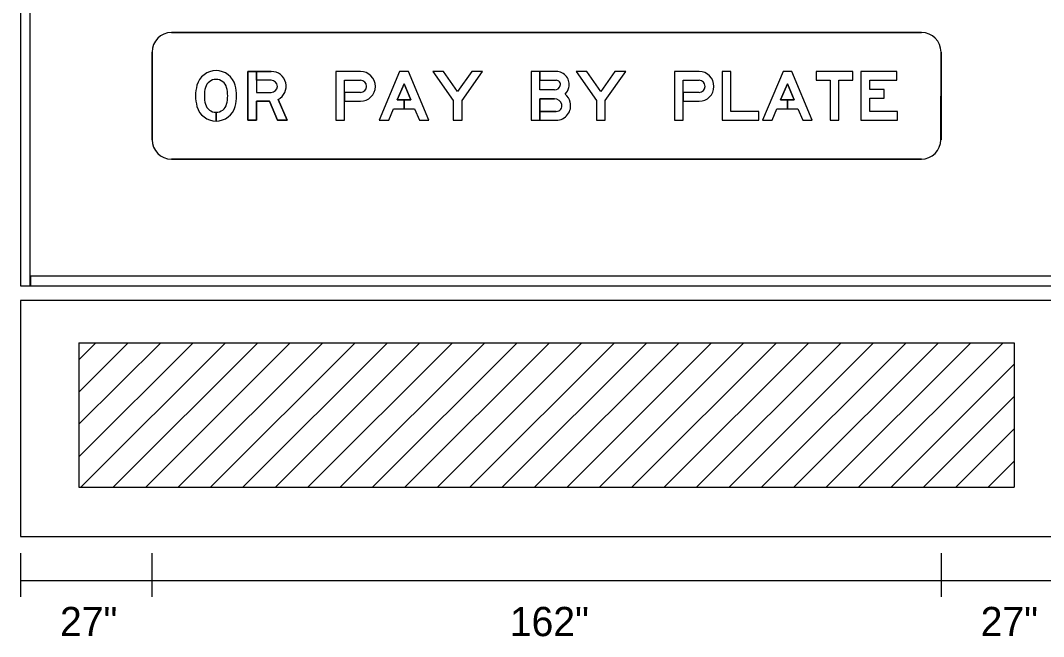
# Model space of a CAD drawing. Extents: x 10268312 to 10268472, y 2142583 to 2142688.
# Drawn here: x 10268433.44 to 10268458.14, y 2142658.39 to 2142673.26 of the extents above; entities that cross this region are included whole.
import ezdxf

# ---------------------------------------------------------------- set-up
doc = ezdxf.new("R2010")
doc.units = 0
for name, color, linetype in [('GSBWFill', 7, 'Continuous'), ('GSDims', 7, 'Continuous'), ('SignPanel', 7, 'Continuous'), ('TextMisc', 7, 'Continuous')]:
    doc.layers.add(name, color=color, linetype=linetype)

msp = doc.modelspace()

# ---------------------------------------------------------------- linework, layer by layer
at = {"layer": 'GSBWFill'}
for p, q in [((10268437.092, 2142672.972), (10268455.198, 2142672.972)), ((10268437.092, 2142672.972), (10268455.198, 2142672.972)), ((10268436.622, 2142670.384), (10268436.622, 2142672.501)), ((10268436.622, 2142670.384), (10268436.622, 2142672.501)), ((10268455.668, 2142672.501), (10268455.668, 2142670.384)), ((10268455.668, 2142672.501), (10268455.668, 2142670.384)), ((10268455.198, 2142669.914), (10268437.092, 2142669.914)), ((10268455.198, 2142669.914), (10268437.092, 2142669.914))]:
    msp.add_line(p, q, dxfattribs=at)
for points in [[(10268433.445, 2142682.673), (10268433.445, 2142666.857), (10268433.68, 2142666.857), (10268433.68, 2142682.673)], [(10268458.61, 2142667.092), (10268433.687, 2142667.092), (10268433.687, 2142666.857), (10268458.845, 2142666.857), (10268458.845, 2142666.857), (10268458.845, 2142682.673)]]:
    msp.add_lwpolyline(points, dxfattribs=at)
for centre, start, end in [((10268437.092, 2142672.501), 90, 180), ((10268437.092, 2142672.501), 90, 180), ((10268455.198, 2142672.501), 0, 90), ((10268455.198, 2142672.501), 0, 90), ((10268437.092, 2142670.384), 180, 270), ((10268437.092, 2142670.384), 180, 270), ((10268455.193, 2142670.384), 270, 0), ((10268455.193, 2142670.384), 270, 0)]:
    msp.add_arc(centre, 0.47, start, end, dxfattribs=at)
at = {"layer": 'GSDims'}
for p, q in [((10268433.445, 2142660.403), (10268433.445, 2142659.345)), ((10268436.62, 2142660.403), (10268436.62, 2142659.345)), ((10268455.67, 2142660.403), (10268455.67, 2142659.345)), ((10268433.445, 2142659.742), (10268436.62, 2142659.742)), ((10268436.62, 2142659.742), (10268455.67, 2142659.742)), ((10268455.67, 2142659.742), (10268458.845, 2142659.742))]:
    msp.add_line(p, q, dxfattribs=at)
at = {"layer": 'SignPanel'}
for p, q in [((10268455.198, 2142672.972), (10268437.092, 2142672.972)), ((10268436.622, 2142672.501), (10268436.622, 2142670.384)), ((10268455.664, 2142670.384), (10268455.668, 2142672.501)), ((10268441.271, 2142671.819), (10268441.653, 2142671.819)), ((10268441.271, 2142671.819), (10268441.653, 2142671.819)), ((10268441.271, 2142671.819), (10268441.653, 2142671.819)), ((10268449.444, 2142671.819), (10268449.826, 2142671.819)), ((10268449.444, 2142671.819), (10268449.826, 2142671.819)), ((10268449.444, 2142671.819), (10268449.826, 2142671.819)), ((10268441.271, 2142671.313), (10268441.653, 2142671.313)), ((10268449.444, 2142671.313), (10268449.826, 2142671.313)), ((10268438.166, 2142670.834), (10268438.166, 2142671.046)), ((10268438.166, 2142671.046), (10268438.166, 2142670.834)), ((10268438.166, 2142670.834), (10268438.166, 2142671.046)), ((10268438.166, 2142671.046), (10268438.166, 2142670.834)), ((10268445.775, 2142670.855), (10268446.38, 2142670.855)), ((10268437.092, 2142669.914), (10268455.193, 2142669.914)), ((10268458.845, 2142666.504), (10268433.445, 2142666.504)), ((10268433.445, 2142666.504), (10268433.445, 2142660.8)), ((10268433.445, 2142660.8), (10268458.845, 2142660.8))]:
    msp.add_line(p, q, dxfattribs=at)
for points in [[(10268439.499, 2142672.031), (10268438.93, 2142672.031), (10268438.93, 2142670.855), (10268439.142, 2142670.855), (10268439.142, 2142671.313), (10268439.454, 2142671.313), (10268439.652, 2142670.855), (10268439.883, 2142670.855), (10268439.666, 2142671.355)], [(10268439.666, 2142671.355), (10268439.883, 2142670.855), (10268439.652, 2142670.855), (10268439.454, 2142671.313), (10268439.142, 2142671.313), (10268439.142, 2142670.855), (10268438.93, 2142670.855), (10268438.93, 2142672.031), (10268439.142, 2142672.031), (10268439.142, 2142671.525), (10268439.499, 2142671.525)], [(10268439.666, 2142671.355), (10268439.883, 2142670.855), (10268439.652, 2142670.855), (10268439.454, 2142671.313), (10268439.142, 2142671.313), (10268439.142, 2142670.855), (10268438.93, 2142670.855), (10268438.93, 2142672.031), (10268439.142, 2142672.031), (10268439.142, 2142671.525), (10268439.499, 2142671.525)], [(10268439.142, 2142671.819), (10268439.142, 2142672.031), (10268439.499, 2142672.031)], [(10268439.142, 2142671.819), (10268439.142, 2142672.031), (10268439.499, 2142672.031)], [(10268441.653, 2142672.031), (10268441.059, 2142672.031), (10268441.059, 2142670.855), (10268441.271, 2142670.855), (10268441.271, 2142671.313)], [(10268441.653, 2142672.031), (10268441.059, 2142672.031), (10268441.059, 2142670.855), (10268441.271, 2142670.855), (10268441.271, 2142671.819)], [(10268441.653, 2142672.031), (10268441.059, 2142672.031), (10268441.059, 2142670.855), (10268441.271, 2142670.855), (10268441.271, 2142671.819)], [(10268446.38, 2142672.031), (10268445.775, 2142672.031), (10268445.775, 2142670.855)], [(10268446.335, 2142671.584), (10268445.986, 2142671.584), (10268445.986, 2142672.031), (10268445.775, 2142672.031), (10268445.775, 2142670.855), (10268445.986, 2142670.855)], [(10268446.335, 2142671.584), (10268445.986, 2142671.584), (10268445.986, 2142672.031), (10268445.775, 2142672.031), (10268445.775, 2142670.855), (10268445.986, 2142670.855)], [(10268446.38, 2142672.031), (10268445.986, 2142672.031), (10268445.986, 2142671.819), (10268446.38, 2142671.819)], [(10268446.38, 2142672.031), (10268445.986, 2142672.031), (10268445.986, 2142671.819), (10268446.38, 2142671.819)], [(10268449.826, 2142672.031), (10268449.232, 2142672.031), (10268449.232, 2142670.855), (10268449.444, 2142670.855), (10268449.444, 2142671.313)], [(10268449.826, 2142672.031), (10268449.232, 2142672.031), (10268449.232, 2142670.855), (10268449.444, 2142670.855), (10268449.444, 2142671.819)], [(10268449.826, 2142672.031), (10268449.232, 2142672.031), (10268449.232, 2142670.855), (10268449.444, 2142670.855), (10268449.444, 2142671.819)], [(10268439.499, 2142671.819), (10268439.142, 2142671.819), (10268439.142, 2142671.525), (10268439.499, 2142671.525)], [(10268439.499, 2142671.819), (10268439.142, 2142671.819)], [(10268439.499, 2142671.819), (10268439.142, 2142671.819)], [(10268441.653, 2142671.525), (10268441.271, 2142671.525), (10268441.271, 2142671.819)], [(10268446.335, 2142671.584), (10268445.986, 2142671.584), (10268445.986, 2142671.819), (10268446.38, 2142671.819)], [(10268449.826, 2142671.525), (10268449.444, 2142671.525), (10268449.444, 2142671.819)], [(10268441.653, 2142671.525), (10268441.271, 2142671.525), (10268441.271, 2142671.313), (10268441.653, 2142671.313)], [(10268441.653, 2142671.525), (10268441.271, 2142671.525), (10268441.271, 2142671.313), (10268441.653, 2142671.313)], [(10268449.826, 2142671.525), (10268449.444, 2142671.525), (10268449.444, 2142671.313), (10268449.826, 2142671.313)], [(10268449.826, 2142671.525), (10268449.444, 2142671.525), (10268449.444, 2142671.313), (10268449.826, 2142671.313)], [(10268446.335, 2142671.372), (10268445.986, 2142671.372), (10268445.986, 2142671.066), (10268446.38, 2142671.066)], [(10268445.986, 2142670.855), (10268445.986, 2142671.372), (10268446.335, 2142671.372)], [(10268445.986, 2142670.855), (10268445.986, 2142671.372), (10268446.335, 2142671.372)], [(10268446.38, 2142671.066), (10268445.986, 2142671.066), (10268445.986, 2142670.855), (10268446.38, 2142670.855)], [(10268446.38, 2142671.066), (10268445.986, 2142671.066), (10268445.986, 2142670.855), (10268446.38, 2142670.855)]]:
    msp.add_lwpolyline(points, dxfattribs=at)
for points in [[(10268442.451, 2142671.131), (10268442.959, 2142671.131), (10268443.075, 2142670.855), (10268443.305, 2142670.855), (10268442.811, 2142672.031), (10268442.599, 2142672.031), (10268442.106, 2142670.855), (10268442.335, 2142670.855)], [(10268442.871, 2142671.343), (10268442.705, 2142671.343), (10268442.705, 2142671.131), (10268442.959, 2142671.131), (10268443.075, 2142670.855), (10268443.305, 2142670.855), (10268442.811, 2142672.031), (10268442.599, 2142672.031), (10268442.106, 2142670.855), (10268442.335, 2142670.855), (10268442.451, 2142671.131), (10268442.705, 2142671.131), (10268442.705, 2142671.343), (10268442.54, 2142671.343), (10268442.705, 2142671.736)], [(10268442.871, 2142671.343), (10268442.705, 2142671.343), (10268442.705, 2142671.131), (10268442.959, 2142671.131), (10268443.075, 2142670.855), (10268443.305, 2142670.855), (10268442.811, 2142672.031), (10268442.599, 2142672.031), (10268442.106, 2142670.855), (10268442.335, 2142670.855), (10268442.451, 2142671.131), (10268442.705, 2142671.131), (10268442.705, 2142671.343), (10268442.54, 2142671.343), (10268442.705, 2142671.736)], [(10268444.105, 2142671.331), (10268444.599, 2142672.031), (10268444.34, 2142672.031), (10268443.999, 2142671.548), (10268443.658, 2142672.031), (10268443.399, 2142672.031), (10268443.893, 2142671.331), (10268443.893, 2142670.855), (10268444.105, 2142670.855)], [(10268444.105, 2142671.331), (10268444.599, 2142672.031), (10268444.34, 2142672.031), (10268443.999, 2142671.548), (10268443.658, 2142672.031), (10268443.399, 2142672.031), (10268443.893, 2142671.331), (10268443.893, 2142670.855), (10268444.105, 2142670.855)], [(10268444.105, 2142671.331), (10268444.599, 2142672.031), (10268444.34, 2142672.031), (10268443.999, 2142671.548), (10268443.658, 2142672.031), (10268443.399, 2142672.031), (10268443.893, 2142671.331), (10268443.893, 2142670.855), (10268444.105, 2142670.855)], [(10268447.562, 2142671.331), (10268448.056, 2142672.031), (10268447.797, 2142672.031), (10268447.456, 2142671.548), (10268447.116, 2142672.031), (10268446.856, 2142672.031), (10268447.35, 2142671.331), (10268447.35, 2142670.855), (10268447.562, 2142670.855)], [(10268447.562, 2142671.331), (10268448.056, 2142672.031), (10268447.797, 2142672.031), (10268447.456, 2142671.548), (10268447.116, 2142672.031), (10268446.856, 2142672.031), (10268447.35, 2142671.331), (10268447.35, 2142670.855), (10268447.562, 2142670.855)], [(10268447.562, 2142671.331), (10268448.056, 2142672.031), (10268447.797, 2142672.031), (10268447.456, 2142671.548), (10268447.116, 2142672.031), (10268446.856, 2142672.031), (10268447.35, 2142671.331), (10268447.35, 2142670.855), (10268447.562, 2142670.855)], [(10268451.266, 2142670.855), (10268451.266, 2142671.061), (10268450.596, 2142671.061), (10268450.596, 2142672.031), (10268450.384, 2142672.031), (10268450.384, 2142670.855)], [(10268451.266, 2142670.855), (10268451.266, 2142671.061), (10268450.596, 2142671.061), (10268450.596, 2142672.031), (10268450.384, 2142672.031), (10268450.384, 2142670.855)], [(10268451.266, 2142670.855), (10268451.266, 2142671.061), (10268450.596, 2142671.061), (10268450.596, 2142672.031), (10268450.384, 2142672.031), (10268450.384, 2142670.855)], [(10268451.706, 2142671.131), (10268452.214, 2142671.131), (10268452.33, 2142670.855), (10268452.56, 2142670.855), (10268452.066, 2142672.031), (10268451.854, 2142672.031), (10268451.36, 2142670.855), (10268451.59, 2142670.855)], [(10268452.125, 2142671.343), (10268451.96, 2142671.343), (10268451.96, 2142671.131), (10268452.214, 2142671.131), (10268452.33, 2142670.855), (10268452.56, 2142670.855), (10268452.066, 2142672.031), (10268451.854, 2142672.031), (10268451.36, 2142670.855), (10268451.59, 2142670.855), (10268451.706, 2142671.131), (10268451.96, 2142671.131), (10268451.96, 2142671.343), (10268451.795, 2142671.343), (10268451.96, 2142671.736)], [(10268452.125, 2142671.343), (10268451.96, 2142671.343), (10268451.96, 2142671.131), (10268452.214, 2142671.131), (10268452.33, 2142670.855), (10268452.56, 2142670.855), (10268452.066, 2142672.031), (10268451.854, 2142672.031), (10268451.36, 2142670.855), (10268451.59, 2142670.855), (10268451.706, 2142671.131), (10268451.96, 2142671.131), (10268451.96, 2142671.343), (10268451.795, 2142671.343), (10268451.96, 2142671.736)], [(10268452.654, 2142671.819), (10268452.989, 2142671.819), (10268452.989, 2142670.855), (10268453.201, 2142670.855), (10268453.201, 2142671.819), (10268453.536, 2142671.819), (10268453.536, 2142672.031), (10268452.654, 2142672.031)], [(10268452.654, 2142671.819), (10268452.989, 2142671.819), (10268452.989, 2142670.855), (10268453.201, 2142670.855), (10268453.201, 2142671.819), (10268453.536, 2142671.819), (10268453.536, 2142672.031), (10268452.654, 2142672.031)], [(10268452.654, 2142671.819), (10268452.989, 2142671.819), (10268452.989, 2142670.855), (10268453.201, 2142670.855), (10268453.201, 2142671.819), (10268453.536, 2142671.819), (10268453.536, 2142672.031), (10268452.654, 2142672.031)], [(10268454.618, 2142671.066), (10268453.948, 2142671.066), (10268453.948, 2142671.383), (10268454.294, 2142671.383), (10268454.294, 2142671.594), (10268453.948, 2142671.594), (10268453.948, 2142671.819), (10268454.6, 2142671.819), (10268454.6, 2142672.031), (10268453.736, 2142672.031), (10268453.736, 2142670.855), (10268454.618, 2142670.855)], [(10268454.618, 2142671.066), (10268453.948, 2142671.066), (10268453.948, 2142671.383), (10268454.294, 2142671.383), (10268454.294, 2142671.594), (10268453.948, 2142671.594), (10268453.948, 2142671.819), (10268454.6, 2142671.819), (10268454.6, 2142672.031), (10268453.736, 2142672.031), (10268453.736, 2142670.855), (10268454.618, 2142670.855)], [(10268454.618, 2142671.066), (10268453.948, 2142671.066), (10268453.948, 2142671.383), (10268454.294, 2142671.383), (10268454.294, 2142671.594), (10268453.948, 2142671.594), (10268453.948, 2142671.819), (10268454.6, 2142671.819), (10268454.6, 2142672.031), (10268453.736, 2142672.031), (10268453.736, 2142670.855), (10268454.618, 2142670.855)], [(10268442.871, 2142671.343), (10268442.705, 2142671.736), (10268442.54, 2142671.343)], [(10268452.125, 2142671.343), (10268451.96, 2142671.736), (10268451.795, 2142671.343)]]:
    msp.add_lwpolyline(points, close=True, dxfattribs=at)
for centre, radius, start, end in [((10268437.092, 2142672.501), 0.47, 90, 180), ((10268455.198, 2142672.501), 0.47, 0, 90), ((10268438.166, 2142671.575), 0.477, 14.9618, 165.0382), ((10268438.166, 2142671.575), 0.477, 14.9618, 165.0382), ((10268438.166, 2142671.575), 0.477, 14.9618, 165.0382), ((10268439.499, 2142671.672), 0.359, 297.837, 90), ((10268439.499, 2142671.672), 0.359, 297.837, 90), ((10268439.499, 2142671.672), 0.359, 297.837, 90), ((10268441.653, 2142671.672), 0.359, 270, 90), ((10268441.653, 2142671.672), 0.359, 270, 90), ((10268441.653, 2142671.672), 0.359, 270, 90), ((10268446.38, 2142671.719), 0.312, 345.5225, 90), ((10268446.38, 2142671.719), 0.312, 345.5225, 90), ((10268446.38, 2142671.719), 0.312, 345.5225, 90), ((10268449.826, 2142671.672), 0.359, 270, 90), ((10268449.826, 2142671.672), 0.359, 270, 90), ((10268449.826, 2142671.672), 0.359, 270, 90), ((10268438.166, 2142671.575), 0.265, 14.9618, 165.0382), ((10268438.166, 2142671.575), 0.265, 14.9618, 165.0382), ((10268438.166, 2142671.575), 0.265, 14.9618, 165.0382), ((10268439.499, 2142671.672), 0.147, 270, 90), ((10268439.499, 2142671.672), 0.147, 270, 90), ((10268439.499, 2142671.672), 0.147, 270, 90), ((10268441.653, 2142671.672), 0.147, 270, 90), ((10268441.653, 2142671.672), 0.147, 270, 90), ((10268441.653, 2142671.672), 0.147, 270, 90), ((10268446.38, 2142671.719), 0.1, 345.5225, 90), ((10268446.38, 2142671.719), 0.1, 345.5225, 90), ((10268446.38, 2142671.719), 0.1, 345.5225, 90), ((10268449.826, 2142671.672), 0.147, 270, 90), ((10268449.826, 2142671.672), 0.147, 270, 90), ((10268449.826, 2142671.672), 0.147, 270, 90), ((10268438.66, 2142671.443), 0.988, 165.0382, 194.9618), ((10268438.66, 2142671.443), 0.988, 165.0382, 194.9618), ((10268438.66, 2142671.443), 0.988, 165.0382, 194.9618), ((10268438.66, 2142671.443), 0.776, 165.0382, 194.9618), ((10268438.66, 2142671.443), 0.776, 165.0382, 194.9618), ((10268438.66, 2142671.443), 0.776, 165.0382, 194.9618), ((10268437.672, 2142671.443), 0.776, 345.0382, 14.9618), ((10268437.672, 2142671.443), 0.776, 345.0382, 14.9618), ((10268437.672, 2142671.443), 0.776, 345.0382, 14.9618), ((10268437.672, 2142671.443), 0.988, 345.0382, 14.9618), ((10268437.672, 2142671.443), 0.988, 345.0382, 14.9618), ((10268437.672, 2142671.443), 0.988, 345.0382, 14.9618), ((10268446.335, 2142671.731), 0.147, 270, 345.5225), ((10268446.335, 2142671.731), 0.147, 270, 345.5225), ((10268446.335, 2142671.731), 0.147, 270, 345.5225), ((10268446.335, 2142671.731), 0.359, 316.7114, 345.5225), ((10268446.335, 2142671.731), 0.359, 316.7114, 345.5225), ((10268446.335, 2142671.731), 0.359, 316.7114, 345.5225), ((10268446.335, 2142671.19), 0.394, 14.4775, 48.4921), ((10268446.335, 2142671.19), 0.394, 14.4775, 48.4921), ((10268446.335, 2142671.19), 0.394, 14.4775, 48.4921), ((10268438.166, 2142671.311), 0.265, 194.9618, 345.0382), ((10268438.166, 2142671.311), 0.265, 194.9618, 270), ((10268438.166, 2142671.311), 0.265, 194.9618, 270), ((10268438.166, 2142671.311), 0.265, 270.0127, 345.0382), ((10268438.166, 2142671.311), 0.265, 270.0127, 345.0382), ((10268446.335, 2142671.19), 0.182, 14.4775, 90), ((10268446.335, 2142671.19), 0.182, 14.4775, 90), ((10268446.335, 2142671.19), 0.182, 14.4775, 90), ((10268446.38, 2142671.202), 0.347, 270, 14.4775), ((10268446.38, 2142671.202), 0.347, 270, 14.4775), ((10268446.38, 2142671.202), 0.347, 270, 14.4775), ((10268446.38, 2142671.202), 0.135, 270, 14.4775), ((10268446.38, 2142671.202), 0.135, 270, 14.4775), ((10268446.38, 2142671.202), 0.135, 270, 14.4775), ((10268438.166, 2142671.311), 0.477, 194.9618, 345.0382), ((10268438.166, 2142671.311), 0.477, 194.9618, 270), ((10268438.166, 2142671.311), 0.477, 194.9618, 270), ((10268438.166, 2142671.311), 0.477, 270.0071, 345.0382), ((10268438.166, 2142671.311), 0.477, 270.0071, 345.0382), ((10268437.092, 2142670.384), 0.47, 180, 270), ((10268455.193, 2142670.384), 0.47, 270, 0)]:
    msp.add_arc(centre, radius, start, end, dxfattribs=at)
at = {"layer": 'TextMisc'}
for p, q in [((10268434.856, 2142665.073), (10268435.265, 2142665.482)), ((10268434.856, 2142664.292), (10268436.048, 2142665.482)), ((10268434.856, 2142663.512), (10268436.83, 2142665.482)), ((10268434.856, 2142662.731), (10268437.612, 2142665.482)), ((10268434.856, 2142665.482), (10268457.434, 2142665.482)), ((10268434.856, 2142665.482), (10268434.856, 2142661.998)), ((10268434.904, 2142661.998), (10268438.395, 2142665.482)), ((10268435.686, 2142661.998), (10268439.177, 2142665.482)), ((10268436.469, 2142661.998), (10268439.959, 2142665.482)), ((10268437.251, 2142661.998), (10268440.741, 2142665.482)), ((10268438.033, 2142661.998), (10268441.524, 2142665.482)), ((10268438.816, 2142661.998), (10268442.306, 2142665.482)), ((10268439.598, 2142661.998), (10268443.088, 2142665.482)), ((10268440.38, 2142661.998), (10268443.871, 2142665.482)), ((10268441.162, 2142661.998), (10268444.653, 2142665.482)), ((10268441.945, 2142661.998), (10268445.435, 2142665.482)), ((10268442.727, 2142661.998), (10268446.218, 2142665.482)), ((10268443.509, 2142661.998), (10268447, 2142665.482)), ((10268444.292, 2142661.998), (10268447.782, 2142665.482)), ((10268445.074, 2142661.998), (10268448.565, 2142665.482)), ((10268445.856, 2142661.998), (10268449.347, 2142665.482)), ((10268446.639, 2142661.998), (10268450.129, 2142665.482)), ((10268447.421, 2142661.998), (10268450.911, 2142665.482)), ((10268448.203, 2142661.998), (10268451.694, 2142665.482)), ((10268448.985, 2142661.998), (10268452.476, 2142665.482)), ((10268449.768, 2142661.998), (10268453.258, 2142665.482)), ((10268450.55, 2142661.998), (10268454.041, 2142665.482)), ((10268451.332, 2142661.998), (10268454.823, 2142665.482)), ((10268452.115, 2142661.998), (10268455.605, 2142665.482)), ((10268452.897, 2142661.998), (10268456.388, 2142665.482)), ((10268453.679, 2142661.998), (10268457.17, 2142665.482)), ((10268457.434, 2142665.482), (10268457.434, 2142661.998)), ((10268454.462, 2142661.998), (10268457.434, 2142664.965)), ((10268455.244, 2142661.998), (10268457.434, 2142664.184)), ((10268456.026, 2142661.998), (10268457.434, 2142663.403)), ((10268456.809, 2142661.998), (10268457.434, 2142662.623)), ((10268434.856, 2142661.998), (10268457.434, 2142661.998))]:
    msp.add_line(p, q, dxfattribs=at)

# ---------------------------------------------------------------- texts
at = {"layer": 'GSDims'}
for s, p in [('27"', (10268434.399, 2142658.398)), ('162"', (10268445.259, 2142658.398)), ('27"', (10268456.625, 2142658.398))]:
    msp.add_text(s, height=0.7056, dxfattribs=at).set_placement(p)

doc.saveas('drawing.dxf')
